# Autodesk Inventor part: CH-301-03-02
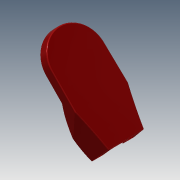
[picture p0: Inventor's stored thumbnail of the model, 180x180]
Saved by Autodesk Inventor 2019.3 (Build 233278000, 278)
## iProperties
Created: 2012-09
Part Number: CH-301-03-02
Material: Ogólny
Document SubType Name: Modeling
Designer: CADENGINEERING4
Density: 1 g/cm^3
Appearance: Czerwona
Author: CADENGINEERING4
Revision Number: ÈÎºÎ
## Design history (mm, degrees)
feature "³é¿Ç1"
node "Bryła1"
